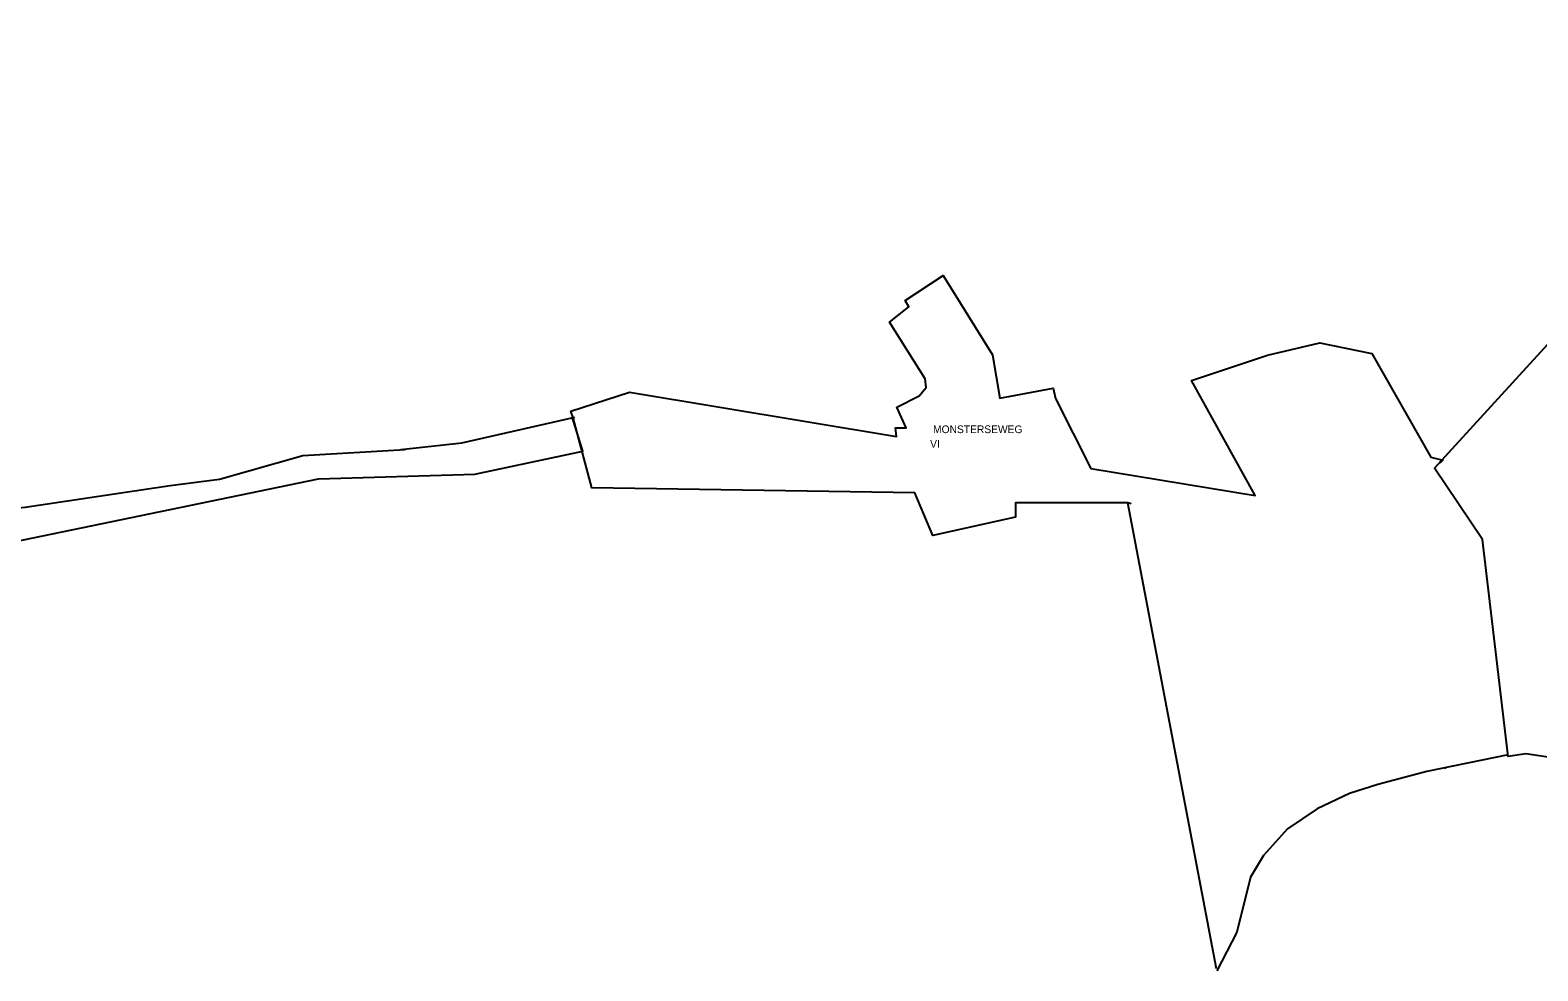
# Model space of a CAD drawing. Extents: x 69068 to 80855, y 440023 to 451362.
# Drawn here: x 72673 to 74444, y 448360 to 449465 of the extents above; entities that cross this region are included whole.
import ezdxf

# ---------------------------------------------------------------- set-up
doc = ezdxf.new("R2010")
doc.units = 0
for name, color, linetype in [('Bemalingsgebiedsgrens', 7, 'Continuous'), ('Bemalingsgebiedsnummer', 7, 'Continuous'), ('RIO_Leidingen', 7, 'Continuous')]:
    doc.layers.add(name, color=color, linetype=linetype)

msp = doc.modelspace()

# ---------------------------------------------------------------- linework, layer by layer
at = {"layer": 'Bemalingsgebiedsgrens'}
for p, q in [((74409.1, 448613.9), (74313.8, 448594.4)), ((74313.8, 448594.4), (74256.2, 448579.3)), ((74222.9, 448568.4), (74184.8, 448550.5)), ((74256.2, 448579.3), (74222.9, 448568.4)), ((74184.8, 448550.5), (74150.2, 448527.1)), ((74150.2, 448527.1), (74121.9, 448495.8)), ((74121.9, 448495.8), (74106.6, 448470.5)), ((74106.6, 448470.5), (74090.4, 448405.8)), ((74090.4, 448405.8), (74067.2, 448360.4))]:
    msp.add_line(p, q, dxfattribs=at)
for points in [[(74469, 448609.2), (74429.9, 448615), (74409.3, 448612.1), (74379.1, 448866.7), (74322.7, 448950.4), (74793, 449464.6)], [(73113.5, 448972.1), (72993.5, 448964.8), (72895.4, 448937.3), (72837.5, 448929.9), (72667.2, 448904.2), (72502.7, 448886.9), (72500.3, 448906.4), (72481.2, 448903.2), (72474.7, 448933.7), (72466, 448983.7), (72463.3, 449028.9), (72430.3, 449116.2), (72394.4, 449192.2), (72374.1, 449240.4), (72357.7, 449318.6)], [(73113.5, 448972.1), (72993.5, 448964.8), (72895.4, 448937.3), (72837.5, 448929.9), (72667.2, 448904.2), (72502.7, 448886.9), (72500.3, 448906.4), (72481.2, 448903.2), (72474.7, 448933.7), (72466, 448983.7), (72463.3, 449028.9), (72430.3, 449116.2), (72394.4, 449192.2), (72374.1, 449240.4), (72357.7, 449318.6)], [(73113.5, 448972.1), (72993.5, 448964.8), (72895.4, 448937.3), (72837.5, 448929.9), (72667.2, 448904.2), (72502.7, 448886.9), (72500.3, 448906.4), (72481.2, 448903.2), (72474.7, 448933.7), (72466, 448983.7), (72463.3, 449028.9), (72430.3, 449116.2), (72394.4, 449192.2), (72374.1, 449240.4), (72357.7, 449318.6)], [(73113.5, 448972.1), (72993.5, 448964.8), (72895.4, 448937.3), (72837.5, 448929.9), (72667.2, 448904.2), (72502.7, 448886.9), (72500.3, 448906.4), (72481.2, 448903.2), (72474.7, 448933.7), (72466, 448983.7), (72463.3, 449028.9), (72430.3, 449116.2), (72394.4, 449192.2), (72374.1, 449240.4), (72357.7, 449318.6)], [(73966.2, 448908.4), (73962.4, 448909.8), (73830.5, 448909.9), (73830.5, 448893.1), (73733.6, 448871.6), (73712.3, 448921.6), (73332.9, 448927.5), (73311, 449009.7), (73308.3, 449017.3), (73376.9, 449039.5), (73690.7, 448987.8), (73689.7, 448997.7), (73702.1, 448997.8), (73691.3, 449022.2), (73717.3, 449035.2), (73725.4, 449045.2), (73724.3, 449055.2), (73682.6, 449121.8), (73705.4, 449139.7), (73701, 449147.3), (73745.4, 449176.5), (73803.4, 449083.4), (73812, 449032.5), (73874.8, 449044.4), (73877.6, 449032.1), (73919.1, 448950.1), (74112, 448918.2), (74037.4, 449053.4), (74126.6, 449083.1), (74187.9, 449097.5), (74249.3, 449084.9), (74318.3, 448963.5), (74332.6, 448959.9), (74329, 448956.5)], [(72335.6, 448807.6), (72494.8, 448829), (72516.7, 448845.2), (72640.5, 448861.4), (73011.7, 448937.9), (73195.3, 448943.3), (73322.3, 448970.6), (73309.6, 449010.8)], [(73108.6, 448972.2), (73180.1, 448980.1), (73312.9, 449010.3)], [(74066.8, 448362.6), (73962.3, 448909.8)], [(74335.6, 448598.1), (74334.6, 448597.9)]]:
    msp.add_lwpolyline(points, dxfattribs=at)

# ---------------------------------------------------------------- texts
at = {"layer": 'Bemalingsgebiedsnummer'}
msp.add_text('VI', height=9, dxfattribs=at).set_placement((73730.2, 448974.4))
at = {"layer": 'RIO_Leidingen'}
msp.add_text('MONSTERSEWEG', height=9, dxfattribs=at).set_placement((73733.7, 448991.6))

doc.saveas('drawing.dxf')
